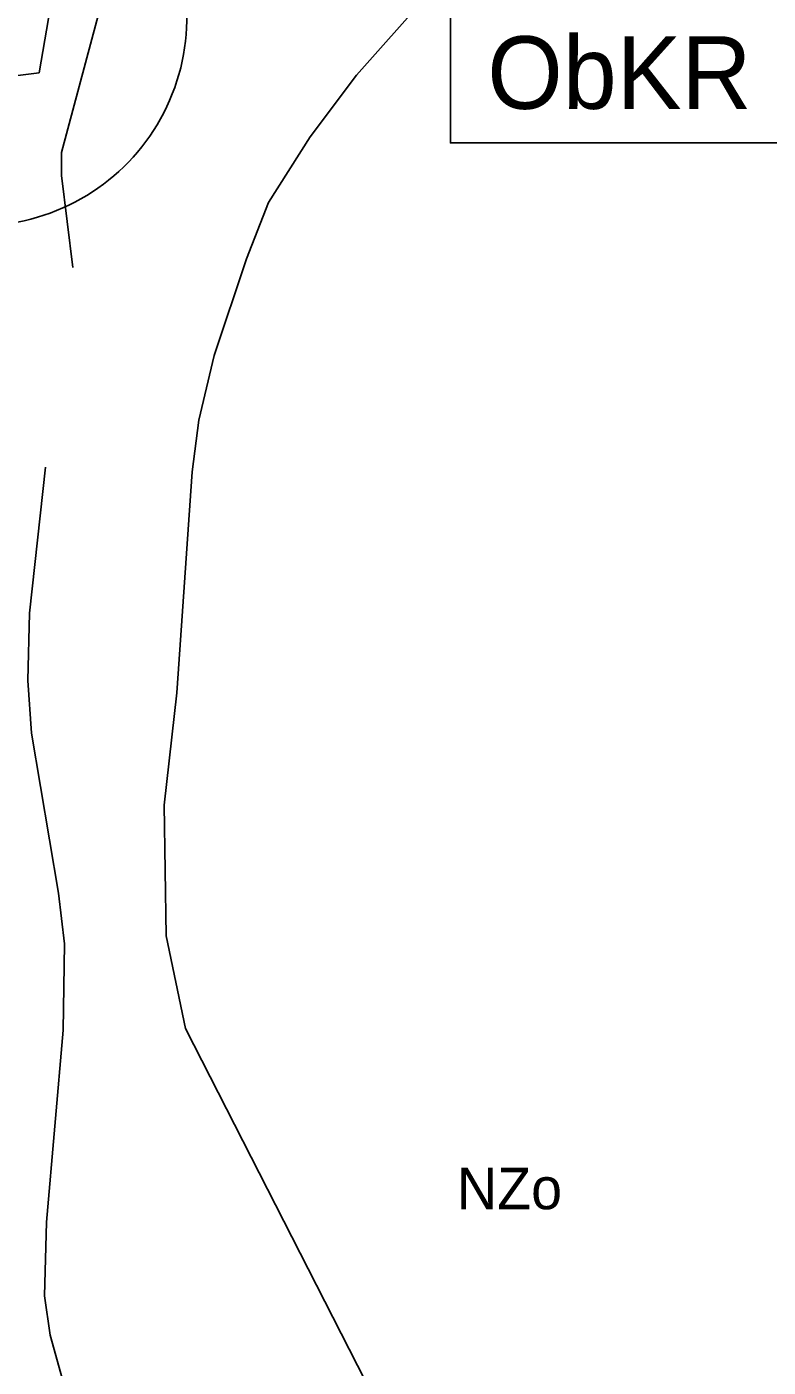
# Model space of a CAD drawing. Extents: x -758499 to -754160, y -1175205 to -1172032.
# Drawn here: x -757016.1 to -756838, y -1174081.3 to -1173759.5 of the extents above; entities that cross this region are included whole.
import ezdxf

# ---------------------------------------------------------------- set-up
doc = ezdxf.new("R2010")
doc.units = 0
for name, color, linetype in [('A017_18_KrajRaz_p', 7, 'Continuous'), ('A040_Les50_p', 7, 'Continuous'), ('A041_BPEJ_p', 7, 'Continuous'), ('A043_InvPuda_p', 7, 'Continuous'), ('indexy RZV_TYP_1', 7, 'Continuous'), ('vrstevnice', 7, 'Continuous')]:
    doc.layers.add(name, color=color, linetype=linetype)

msp = doc.modelspace()

# ---------------------------------------------------------------- linework, layer by layer
at = {"layer": 'A017_18_KrajRaz_p'}
msp.add_lwpolyline([(-756914.35, -1173756.15), (-756803.35, -1173756.15), (-756803.35, -1173787.4), (-756914.35, -1173787.4)], close=True, dxfattribs=at)
at = {"layer": 'A040_Les50_p'}
msp.add_arc((-757027.66, -1173757.28), 50, 278.8156, 38.0679, dxfattribs=at)
at = {"layer": 'A041_BPEJ_p'}
for p, q in [((-756907.36, -1173737.87), (-756936.93, -1173771.12)), ((-756936.93, -1173771.12), (-756907.36, -1173737.87)), ((-756936.93, -1173771.12), (-756948.01, -1173785.9)), ((-756948.01, -1173785.9), (-756936.93, -1173771.12)), ((-756948.01, -1173785.9), (-756958.04, -1173801.74)), ((-756958.04, -1173801.74), (-756948.01, -1173785.9)), ((-756958.04, -1173801.74), (-756963.32, -1173815.2)), ((-756963.32, -1173815.2), (-756958.04, -1173801.74)), ((-756963.32, -1173815.2), (-756971.1, -1173838.43)), ((-756971.1, -1173838.43), (-756963.32, -1173815.2)), ((-756971.1, -1173838.43), (-756974.8, -1173854)), ((-756974.8, -1173854), (-756971.1, -1173838.43)), ((-756974.8, -1173854), (-756976.38, -1173866.4)), ((-756976.38, -1173866.4), (-756974.8, -1173854)), ((-756976.38, -1173866.4), (-756980.08, -1173919.45)), ((-756980.08, -1173919.45), (-756976.38, -1173866.4)), ((-756980.08, -1173919.45), (-756983.11, -1173946.37)), ((-756983.11, -1173946.37), (-756980.08, -1173919.45)), ((-756983.11, -1173946.37), (-756982.59, -1173977.78)), ((-756982.59, -1173977.78), (-756983.11, -1173946.37)), ((-756982.59, -1173977.78), (-756977.97, -1174000)), ((-756977.97, -1174000), (-756982.59, -1173977.78)), ((-756977.97, -1174000), (-756924.23, -1174105.22)), ((-756924.23, -1174105.22), (-756977.97, -1174000))]:
    msp.add_line(p, q, dxfattribs=at)
at = {"layer": 'A043_InvPuda_p'}
for p, q in [((-757013.11, -1173770.56), (-756972.62, -1173531.04)), ((-757168.06, -1173790.21), (-757013.11, -1173770.56))]:
    msp.add_line(p, q, dxfattribs=at)
at = {"layer": 'vrstevnice'}
for p, q in [((-756996.67, -1173748.17), (-757007.79, -1173789.68)), ((-757007.79, -1173789.68), (-757007.78, -1173795.22)), ((-757007.78, -1173795.22), (-757005.09, -1173817.28)), ((-757011.65, -1173865.27), (-757015.43, -1173900.29)), ((-757015.43, -1173900.29), (-757015.86, -1173916.45)), ((-757015.86, -1173916.45), (-757014.99, -1173929.15)), ((-757014.99, -1173929.15), (-757008.5, -1173967.54)), ((-757008.5, -1173967.54), (-757007.06, -1173979.67)), ((-757007.06, -1173979.67), (-757007.35, -1174000.45)), ((-757007.35, -1174000.45), (-757011.39, -1174046.49)), ((-757011.39, -1174046.49), (-757011.82, -1174064.24)), ((-757011.82, -1174064.24), (-757010.52, -1174073.62)), ((-757010.52, -1174073.62), (-757006.13, -1174089.3))]:
    msp.add_line(p, q, dxfattribs=at)

# ---------------------------------------------------------------- texts
at = {"layer": 'A017_18_KrajRaz_p'}
msp.add_text('ObKR 23', height=17.43, dxfattribs=at).set_placement((-756905.47, -1173779.22))
at = {"layer": 'indexy RZV_TYP_1'}
msp.add_text('NZo', height=10, dxfattribs=at).set_placement((-756912.77, -1174043.42))

doc.saveas('drawing.dxf')
